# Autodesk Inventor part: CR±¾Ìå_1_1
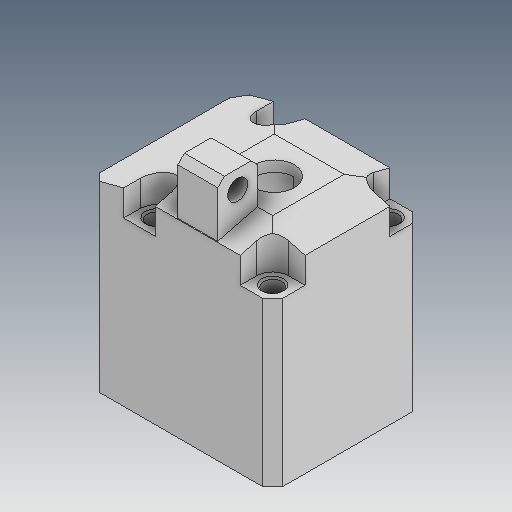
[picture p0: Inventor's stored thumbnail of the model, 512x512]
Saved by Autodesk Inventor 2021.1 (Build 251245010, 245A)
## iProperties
Created: 2019-04
Part Number: CR±¾Ìå_1_1
Material: Ogólny
Document SubType Name: Modeling
Designer: user
Density: 1 g/cm^3
Appearance: Domyślna
Author: user
Revision Number: ÈÎºÎ
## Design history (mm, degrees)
feature "ÊäÈë1"
feature "ÊäÈë2"
feature "ÊäÈë3"
feature "ÊäÈë4"
node "Bryła1"
node "Bryła2"
node "Bryła3"
node "Bryła4"
